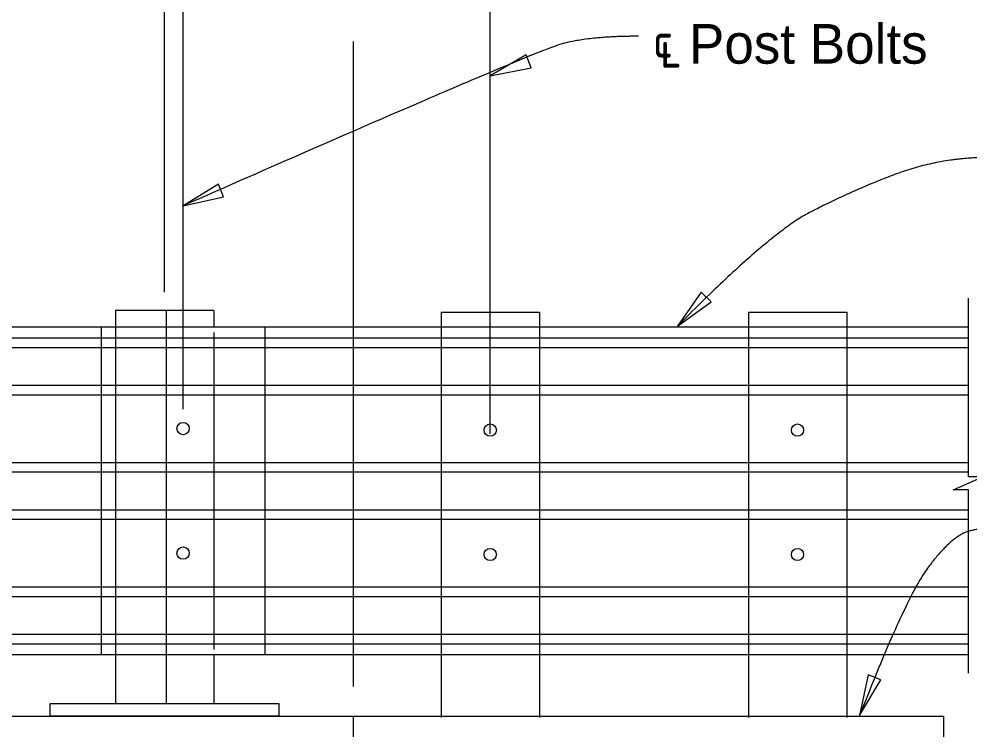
# Model space of a CAD drawing. Extents: x 21587 to 21656.3, y 56117.4 to 56157.3.
# Drawn here: x 21619.149 to 21623.985, y 56134.73 to 56138.347 of the extents above; entities that cross this region are included whole.
import ezdxf

# ---------------------------------------------------------------- set-up
doc = ezdxf.new("R2010")
doc.units = 0
for name, color, linetype in [('AdhocPoint_dp', 7, 'Continuous'), ('Border', 7, 'Continuous'), ('Patterning', 7, 'Continuous'), ('PlotBorder_dp', 7, 'Continuous'), ('SheetBorder_dp', 7, 'Continuous'), ('SubStrConc', 7, 'Continuous'), ('TextMisc', 7, 'Continuous')]:
    doc.layers.add(name, color=color, linetype=linetype)

msp = doc.modelspace()

# ---------------------------------------------------------------- linework, layer by layer
at = {"layer": 'AdhocPoint_dp'}
msp.add_line((21613.608, 56134.8009), (21621.5551, 56134.8009), dxfattribs=at)
at = {"layer": 'Border'}
for p, q in [((21620.1393, 56136.8635), (21619.6393, 56136.8635)), ((21619.6393, 56136.8635), (21619.6393, 56136.7802)), ((21620.1393, 56136.8635), (21620.1393, 56136.7802)), ((21619.5663, 56136.7801), (21607.3117, 56136.7801)), ((21607.3117, 56136.7246), (21619.5663, 56136.7246)), ((21607.3117, 56136.6764), (21619.5663, 56136.6764)), ((21607.3117, 56136.4835), (21619.5663, 56136.4835)), ((21607.3117, 56136.4353), (21619.5663, 56136.4353)), ((21607.3117, 56136.0914), (21619.5663, 56136.0914)), ((21607.3117, 56136.0431), (21619.5663, 56136.0431)), ((21607.3117, 56135.8503), (21619.5663, 56135.8503)), ((21607.3117, 56135.8022), (21619.5663, 56135.8022)), ((21607.3117, 56135.4582), (21619.5663, 56135.4582)), ((21607.3117, 56135.41), (21619.5663, 56135.41)), ((21607.3117, 56135.2172), (21619.5663, 56135.2172)), ((21607.3117, 56135.169), (21619.5663, 56135.169)), ((21619.5663, 56135.1134), (21607.3117, 56135.1134)), ((21619.6393, 56135.1134), (21619.6393, 56134.8635)), ((21620.1393, 56135.1135), (21620.1393, 56134.8635)), ((21620.4726, 56134.8635), (21619.306, 56134.8635)), ((21619.306, 56134.8635), (21619.306, 56134.801)), ((21620.1393, 56134.8635), (21619.6393, 56134.8635)), ((21620.4726, 56134.801), (21620.4726, 56134.8635)), ((21620.4726, 56134.801), (21619.306, 56134.801))]:
    msp.add_line(p, q, dxfattribs=at)
for centre in [(21619.983, 56136.2634), (21619.983, 56135.6303)]:
    msp.add_circle(centre, 0.0312, dxfattribs=at)
at = {"layer": 'Patterning'}
for p, q in [((21619.8997, 56134.8635), (21619.8997, 56136.8635)), ((21623.978, 56136.78), (21619.5663, 56136.78)), ((21619.6393, 56136.78), (21619.6393, 56135.1134)), ((21620.1393, 56136.7516), (21620.1393, 56135.1398)), ((21623.978, 56135.1134), (21619.5663, 56135.1134))]:
    msp.add_line(p, q, dxfattribs=at)
for centre in [(21621.5456, 56136.2559), (21623.1081, 56136.2559), (21621.5456, 56135.6228), (21623.1081, 56135.6228)]:
    msp.add_circle(centre, 0.0312, dxfattribs=at)
at = {"layer": 'PlotBorder_dp'}
msp.add_line((21620.8499, 56134.9508), (21620.8499, 56138.2324), dxfattribs=at)
for points in [[(21621.5456, 56138.0578), (21621.7529, 56138.0984), (21621.7279, 56138.1644)], [(21619.9831, 56137.3964), (21620.1894, 56137.4417), (21620.1629, 56137.5071)], [(21622.4973, 56136.7845), (21622.6689, 56136.9078), (21622.6187, 56136.9574)], [(21623.4241, 56134.8039), (21623.5326, 56134.9852), (21623.4668, 56135.0108)]]:
    msp.add_lwpolyline(points, close=True, dxfattribs=at)
msp.add_lwpolyline([(21623.978, 56135.0198), (21623.978, 56135.9514), (21623.9005, 56135.9514), (21624.0505, 56136.0177), (21623.978, 56136.0177), (21623.978, 56136.9265)], dxfattribs=at)
for points in [[(21622.2989, 56138.259), (21622.0536, 56138.259), (21621.7685, 56138.1827), (21619.9831, 56137.3964)], [(21624.0822, 56137.6421), (21623.8314, 56137.6421), (21623.38, 56137.4716), (21622.9637, 56137.256), (21622.4973, 56136.7845)], [(21624.2687, 56135.7655), (21624.0532, 56135.7655), (21623.8906, 56135.7125), (21623.6609, 56135.412), (21623.4241, 56134.8039)]]:
    msp.add_open_spline(points, degree=2, dxfattribs=at)
at = {"layer": 'SubStrConc'}
for p, q in [((21620.8499, 56134.0509), (21620.8499, 56134.8009)), ((21620.8499, 56134.8009), (21623.8499, 56134.8009)), ((21623.8499, 56134.8009), (21623.8499, 56134.0509))]:
    msp.add_line(p, q, dxfattribs=at)
at = {"layer": 'TextMisc'}
for p, q in [((21619.9831, 56136.3623), (21619.9831, 56141.4203)), ((21619.8893, 56136.9565), (21619.8893, 56139.3215)), ((21621.5456, 56136.2372), (21621.5456, 56138.6051)), ((21621.2956, 56136.856), (21621.2956, 56134.7935)), ((21621.2956, 56136.856), (21621.7956, 56136.856)), ((21621.7956, 56136.856), (21621.7956, 56134.7935)), ((21622.8581, 56136.856), (21622.8581, 56134.7935)), ((21622.8581, 56136.856), (21623.3581, 56136.856)), ((21623.3581, 56136.856), (21623.3581, 56134.7935)), ((21619.5663, 56136.7802), (21619.5663, 56135.1135)), ((21620.3996, 56136.7802), (21620.3996, 56135.1135)), ((21619.5663, 56136.7245), (21623.978, 56136.7245)), ((21619.5663, 56136.6763), (21623.978, 56136.6763)), ((21619.5663, 56136.4835), (21623.978, 56136.4835)), ((21619.5663, 56136.4353), (21623.978, 56136.4353)), ((21619.5663, 56136.0913), (21623.978, 56136.0913)), ((21619.5663, 56136.0431), (21623.978, 56136.0431)), ((21619.5663, 56135.8503), (21623.978, 56135.8503)), ((21619.5663, 56135.8021), (21623.978, 56135.8021)), ((21619.5663, 56135.4582), (21623.978, 56135.4582)), ((21619.5663, 56135.4099), (21623.978, 56135.4099)), ((21619.5663, 56135.2171), (21623.978, 56135.2171)), ((21619.5663, 56135.1689), (21623.978, 56135.1689))]:
    msp.add_line(p, q, dxfattribs=at)

# ---------------------------------------------------------------- texts
at = {"layer": 'SheetBorder_dp'}
msp.add_text('℄ Post Bolts', height=0.2016, dxfattribs=at).set_placement((21622.3718, 56138.1196))

doc.saveas('drawing.dxf')
